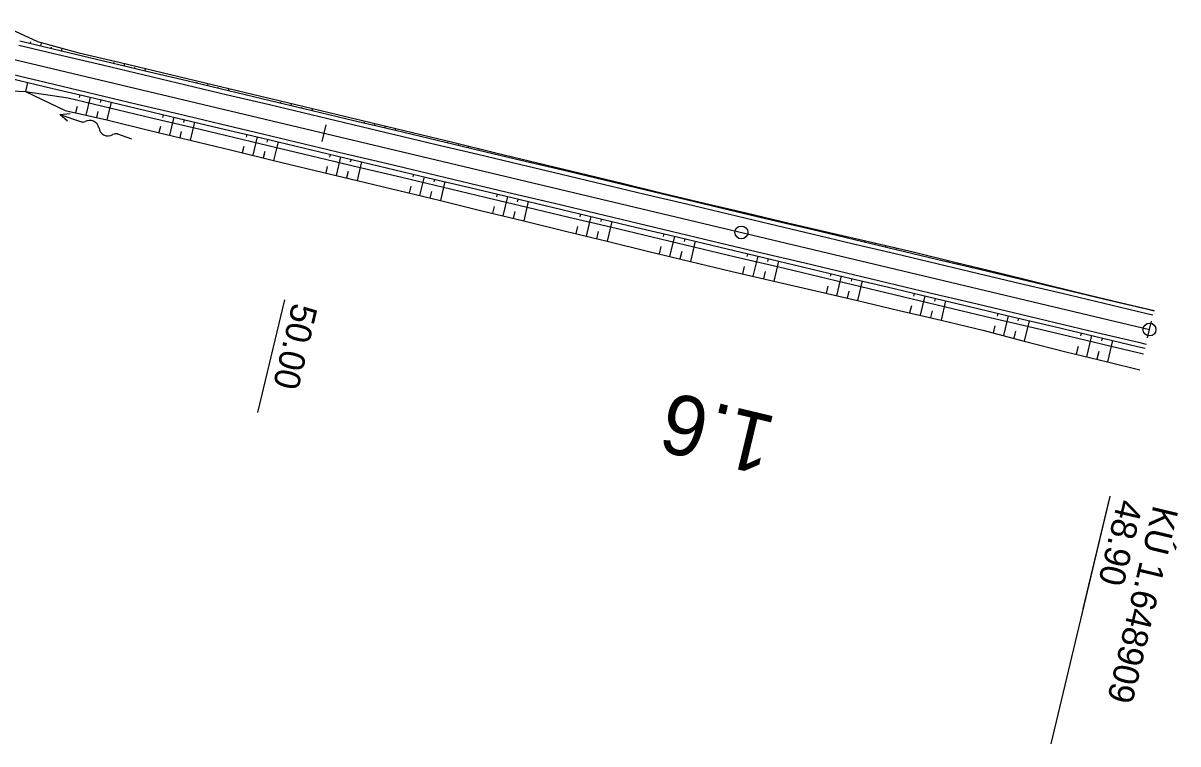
# Model space of a CAD drawing. Extents: x -481656 to -478728, y -1113199 to -1110710.
# Drawn here: x -478863.1 to -478728.5, y -1110802.4 to -1110718.3 of the extents above; entities that cross this region are included whole.
import ezdxf

# ---------------------------------------------------------------- set-up
doc = ezdxf.new("R2010")
doc.units = 0
for name, color, linetype in [('C5_HATCH_SLOPE_L', 7, 'Continuous'), ('C5_HATCH_SLOPE_R', 7, 'Continuous'), ('C5_HECTOMETRY', 7, 'Continuous'), ('C5_HLBODY', 7, 'Continuous'), ('C5_HRANA_TELESO', 7, 'Continuous'), ('C5_KORUNA', 7, 'Continuous'), ('C5_OSA', 7, 'Continuous'), ('C5_PRIKOP', 7, 'Continuous'), ('C5_STANICENI', 7, 'Continuous'), ('C5_ZPEVKRAJ', 7, 'Continuous'), ('DRENÁŽ', 7, 'Continuous'), ('PLYN', 7, 'Continuous')]:
    doc.layers.add(name, color=color, linetype=linetype)

# ---------------------------------------------------------------- blocks, each defined once
blk = doc.blocks.new('A$C70B')
at = {"layer": 'DRENÁŽ'}
for p, q in [((0.87, 0), (-0.87, 0)), ((6.86, 0.43), (7.97, 0)), ((7.97, 0), (5.28, 0)), ((7.97, 0), (6.86, -0.48))]:
    blk.add_line(p, q, dxfattribs=at)
for centre, radius, start, end in [((0.87, 0.58), 0.582, 269.6924, 322.7901), ((2.17, -0.42), 1.05, 24.4039, 142.0836), ((4.08, 0.59), 1.11, 210.8873, 317.3707), ((5.32, -0.64), 0.636, 85.9766, 131.7248)]:
    blk.add_arc(centre, radius, start, end, dxfattribs=at)

msp = doc.modelspace()

# ---------------------------------------------------------------- linework, layer by layer
at = {"layer": 'C5_HATCH_SLOPE_L'}
for p, q in [((-478862.24, -1110720.66), (-478862.2, -1110720.48)), ((-478862.16, -1110720.3), (-478862.16, -1110720.3)), ((-478861.03, -1110720.95), (-478860.95, -1110720.63)), ((-478859.81, -1110721.24), (-478859.78, -1110721.1)), ((-478859.75, -1110720.96), (-478859.75, -1110720.96)), ((-478858.6, -1110721.53), (-478858.54, -1110721.29)), ((-478852.52, -1110722.98), (-478852.49, -1110722.85)), ((-478852.46, -1110722.73), (-478852.46, -1110722.73)), ((-478851.3, -1110723.27), (-478851.24, -1110723.02)), ((-478850.09, -1110723.56), (-478850.06, -1110723.43)), ((-478850.03, -1110723.31), (-478850.03, -1110723.31)), ((-478848.87, -1110723.85), (-478848.81, -1110723.6)), ((-478842.79, -1110725.29), (-478842.76, -1110725.18)), ((-478842.73, -1110725.06), (-478842.73, -1110725.06)), ((-478841.57, -1110725.58), (-478841.52, -1110725.36)), ((-478840.36, -1110725.87), (-478840.33, -1110725.76)), ((-478840.3, -1110725.65), (-478840.3, -1110725.65)), ((-478839.14, -1110726.16), (-478839.09, -1110725.94)), ((-478833.06, -1110727.61), (-478833.04, -1110727.51)), ((-478833.01, -1110727.4), (-478833.01, -1110727.4)), ((-478831.85, -1110727.9), (-478831.8, -1110727.7)), ((-478830.63, -1110728.19), (-478830.61, -1110728.09)), ((-478830.58, -1110727.99), (-478830.58, -1110727.99)), ((-478829.41, -1110728.48), (-478829.37, -1110728.28)), ((-478823.33, -1110729.93), (-478823.31, -1110729.83)), ((-478823.29, -1110729.73), (-478823.29, -1110729.73)), ((-478822.12, -1110730.22), (-478822.07, -1110730.03)), ((-478820.9, -1110730.51), (-478820.88, -1110730.41)), ((-478820.86, -1110730.32), (-478820.86, -1110730.32)), ((-478819.69, -1110730.8), (-478819.64, -1110730.61)), ((-478813.61, -1110732.25), (-478813.59, -1110732.16)), ((-478813.57, -1110732.08), (-478813.57, -1110732.08)), ((-478812.39, -1110732.54), (-478812.35, -1110732.37)), ((-478811.17, -1110732.82), (-478811.16, -1110732.75)), ((-478811.14, -1110732.67), (-478811.14, -1110732.67)), ((-478809.96, -1110733.11), (-478809.92, -1110732.96)), ((-478803.88, -1110734.56), (-478803.86, -1110734.5)), ((-478803.85, -1110734.43), (-478803.85, -1110734.43)), ((-478802.66, -1110734.85), (-478802.63, -1110734.72)), ((-478801.45, -1110735.14), (-478801.43, -1110735.08)), ((-478801.42, -1110735.02), (-478801.42, -1110735.02)), ((-478800.23, -1110735.43), (-478800.2, -1110735.31)), ((-478794.15, -1110736.88), (-478794.14, -1110736.83)), ((-478794.13, -1110736.78), (-478794.13, -1110736.78)), ((-478792.93, -1110737.17), (-478792.91, -1110737.07)), ((-478791.72, -1110737.46), (-478791.71, -1110737.41)), ((-478791.7, -1110737.36), (-478791.7, -1110737.36)), ((-478790.5, -1110737.75), (-478790.48, -1110737.66)), ((-478784.42, -1110739.2), (-478784.41, -1110739.16)), ((-478784.4, -1110739.12), (-478784.4, -1110739.12)), ((-478783.21, -1110739.49), (-478783.19, -1110739.41)), ((-478781.99, -1110739.78), (-478781.98, -1110739.74)), ((-478781.97, -1110739.7), (-478781.97, -1110739.7)), ((-478780.78, -1110740.07), (-478780.76, -1110739.99)), ((-478774.7, -1110741.52), (-478774.68, -1110741.46)), ((-478774.67, -1110741.41), (-478774.67, -1110741.41)), ((-478773.48, -1110741.8), (-478773.45, -1110741.7)), ((-478772.26, -1110742.09), (-478772.25, -1110742.04)), ((-478772.24, -1110741.98), (-478772.24, -1110741.98)), ((-478771.05, -1110742.38), (-478771.02, -1110742.27)), ((-478764.97, -1110743.83), (-478764.95, -1110743.76)), ((-478764.93, -1110743.7), (-478764.93, -1110743.7)), ((-478763.75, -1110744.12), (-478763.72, -1110743.98)), ((-478762.54, -1110744.41), (-478762.52, -1110744.34)), ((-478762.5, -1110744.27), (-478762.5, -1110744.27)), ((-478761.32, -1110744.7), (-478761.28, -1110744.55)), ((-478755.24, -1110746.15), (-478755.22, -1110746.07)), ((-478755.2, -1110745.99), (-478755.2, -1110745.99)), ((-478754.02, -1110746.44), (-478753.99, -1110746.29)), ((-478752.81, -1110746.73), (-478752.79, -1110746.66)), ((-478752.77, -1110746.58), (-478752.77, -1110746.58)), ((-478751.59, -1110747.02), (-478751.56, -1110746.88)), ((-478745.51, -1110748.47), (-478745.5, -1110748.43)), ((-478745.49, -1110748.39), (-478745.49, -1110748.39)), ((-478744.29, -1110748.76), (-478744.28, -1110748.7)), ((-478743.08, -1110749.05), (-478743.08, -1110749.03)), ((-478743.07, -1110749.01), (-478743.07, -1110749.01)), ((-478741.86, -1110749.33), (-478741.86, -1110749.32)), ((-478735.78, -1110750.76), (-478735.78, -1110750.76)), ((-478735.78, -1110750.78), (-478735.78, -1110750.77)), ((-478734.57, -1110751.07), (-478734.56, -1110751.05)), ((-478733.35, -1110751.34), (-478733.35, -1110751.34)), ((-478733.35, -1110751.36), (-478733.35, -1110751.35)), ((-478732.14, -1110751.65), (-478732.13, -1110751.63))]:
    msp.add_line(p, q, dxfattribs=at)
at = {"layer": 'C5_HATCH_SLOPE_R'}
for p, q in [((-478862.57, -1110725.21), (-478862.82, -1110726.29)), ((-478856.49, -1110726.66), (-478856.56, -1110726.98)), ((-478855.27, -1110726.95), (-478855.77, -1110729.04)), ((-478854.05, -1110727.24), (-478854.13, -1110727.56)), ((-478856.81, -1110728.03), (-478856.99, -1110728.76)), ((-478854.38, -1110728.6), (-478854.55, -1110729.32)), ((-478852.84, -1110727.53), (-478853.33, -1110729.6)), ((-478846.76, -1110728.98), (-478846.84, -1110729.3)), ((-478845.54, -1110729.26), (-478846.04, -1110731.36)), ((-478844.33, -1110729.55), (-478844.4, -1110729.88)), ((-478843.11, -1110729.84), (-478843.61, -1110731.95)), ((-478847.09, -1110730.35), (-478847.26, -1110731.07)), ((-478844.65, -1110730.93), (-478844.83, -1110731.66)), ((-478837.03, -1110731.29), (-478837.11, -1110731.62)), ((-478835.82, -1110731.58), (-478836.32, -1110733.72)), ((-478834.6, -1110731.87), (-478834.68, -1110732.2)), ((-478833.38, -1110732.16), (-478833.89, -1110734.31)), ((-478837.36, -1110732.68), (-478837.54, -1110733.43)), ((-478834.93, -1110733.27), (-478835.11, -1110734.01)), ((-478827.3, -1110733.61), (-478827.38, -1110733.93)), ((-478826.09, -1110733.9), (-478826.6, -1110736.07)), ((-478827.64, -1110735.02), (-478827.82, -1110735.78)), ((-478824.87, -1110734.19), (-478824.95, -1110734.51)), ((-478823.66, -1110734.48), (-478824.17, -1110736.65)), ((-478825.21, -1110735.6), (-478825.39, -1110736.36)), ((-478817.58, -1110735.93), (-478817.65, -1110736.25)), ((-478816.36, -1110736.22), (-478816.88, -1110738.41)), ((-478815.14, -1110736.51), (-478815.22, -1110736.83)), ((-478817.91, -1110737.34), (-478818.1, -1110738.11)), ((-478815.48, -1110737.93), (-478815.67, -1110738.71)), ((-478813.93, -1110736.79), (-478814.45, -1110739)), ((-478807.85, -1110738.24), (-478807.92, -1110738.57)), ((-478806.63, -1110738.53), (-478807.17, -1110740.78)), ((-478805.42, -1110738.82), (-478805.49, -1110739.15)), ((-478804.2, -1110739.11), (-478804.74, -1110741.37)), ((-478808.19, -1110739.69), (-478808.38, -1110740.48)), ((-478805.76, -1110740.27), (-478805.95, -1110741.08)), ((-478798.12, -1110740.56), (-478798.2, -1110740.89)), ((-478798.47, -1110742.03), (-478798.67, -1110742.85)), ((-478796.9, -1110740.85), (-478797.45, -1110743.15)), ((-478795.69, -1110741.14), (-478795.76, -1110741.46)), ((-478794.47, -1110741.43), (-478795.02, -1110743.74)), ((-478796.04, -1110742.62), (-478796.24, -1110743.45)), ((-478788.39, -1110742.88), (-478788.47, -1110743.2)), ((-478787.17, -1110743.17), (-478787.73, -1110745.52)), ((-478788.75, -1110744.37), (-478788.95, -1110745.22)), ((-478785.96, -1110743.46), (-478786.04, -1110743.78)), ((-478784.74, -1110743.75), (-478785.31, -1110746.11)), ((-478786.32, -1110744.96), (-478786.52, -1110745.81)), ((-478778.66, -1110745.2), (-478778.74, -1110745.52)), ((-478777.45, -1110745.49), (-478778.01, -1110747.83)), ((-478776.23, -1110745.77), (-478776.31, -1110746.1)), ((-478775.02, -1110746.06), (-478775.57, -1110748.4)), ((-478779.02, -1110746.7), (-478779.22, -1110747.55)), ((-478776.59, -1110747.27), (-478776.79, -1110748.12)), ((-478768.94, -1110747.51), (-478769.01, -1110747.84)), ((-478767.72, -1110747.8), (-478768.27, -1110750.11)), ((-478766.5, -1110748.09), (-478766.58, -1110748.42)), ((-478765.29, -1110748.38), (-478765.83, -1110750.67)), ((-478769.29, -1110748.99), (-478769.49, -1110749.82)), ((-478766.85, -1110749.56), (-478767.05, -1110750.39)), ((-478759.21, -1110749.83), (-478759.29, -1110750.15)), ((-478757.99, -1110750.12), (-478758.53, -1110752.37)), ((-478759.55, -1110751.28), (-478759.75, -1110752.09)), ((-478756.78, -1110750.41), (-478756.85, -1110750.73)), ((-478755.56, -1110750.7), (-478756.09, -1110752.94)), ((-478757.12, -1110751.86), (-478757.31, -1110752.65)), ((-478749.48, -1110752.15), (-478749.56, -1110752.47)), ((-478748.26, -1110752.44), (-478748.82, -1110754.75)), ((-478747.05, -1110752.73), (-478747.12, -1110753.05)), ((-478749.83, -1110753.61), (-478750.02, -1110754.43)), ((-478745.83, -1110753.02), (-478746.4, -1110755.4)), ((-478747.41, -1110754.22), (-478747.61, -1110755.07)), ((-478739.75, -1110754.46), (-478739.83, -1110754.79)), ((-478738.54, -1110754.75), (-478739.13, -1110757.23)), ((-478737.32, -1110755.04), (-478737.4, -1110755.37)), ((-478736.1, -1110755.33), (-478736.7, -1110757.81)), ((-478740.12, -1110756.02), (-478740.34, -1110756.94)), ((-478737.69, -1110756.61), (-478737.91, -1110757.52))]:
    msp.add_line(p, q, dxfattribs=at)
at = {"layer": 'C5_HECTOMETRY'}
msp.add_circle((-478779.36, -1110742.72), 0.75, dxfattribs=at)
at = {"layer": 'C5_HLBODY'}
msp.add_line((-478736.41, -1110773.51), (-478743.3, -1110802.4), dxfattribs=at)
msp.add_circle((-478731.78, -1110754.05), 0.75, dxfattribs=at)
at = {"layer": 'C5_HRANA_TELESO'}
for p, q in [((-478866.06, -1110718.29), (-478861.43, -1110720.45)), ((-478861.43, -1110720.45), (-478856.6, -1110721.75)), ((-478856.6, -1110721.75), (-478851.73, -1110722.88)), ((-478851.73, -1110722.88), (-478846.87, -1110724.05)), ((-478846.87, -1110724.05), (-478842.01, -1110725.22)), ((-478842.01, -1110725.22), (-478837.15, -1110726.4)), ((-478867.9, -1110726), (-478862.82, -1110726.29)), ((-478862.82, -1110726.29), (-478858.21, -1110728.48)), ((-478837.15, -1110726.4), (-478832.29, -1110727.57)), ((-478858.21, -1110728.48), (-478853.33, -1110729.6)), ((-478832.29, -1110727.57), (-478827.43, -1110728.73)), ((-478853.33, -1110729.6), (-478848.47, -1110730.77)), ((-478827.43, -1110728.73), (-478822.56, -1110729.89)), ((-478822.56, -1110729.89), (-478817.7, -1110731.07)), ((-478848.47, -1110730.77), (-478843.61, -1110731.95)), ((-478817.7, -1110731.07), (-478812.84, -1110732.24)), ((-478843.61, -1110731.95), (-478838.75, -1110733.13)), ((-478812.84, -1110732.24), (-478807.98, -1110733.42)), ((-478838.75, -1110733.13), (-478833.89, -1110734.31)), ((-478807.98, -1110733.42), (-478803.12, -1110734.59)), ((-478833.89, -1110734.31), (-478829.04, -1110735.49)), ((-478803.12, -1110734.59), (-478798.26, -1110735.77)), ((-478829.04, -1110735.49), (-478824.17, -1110736.65)), ((-478824.17, -1110736.65), (-478819.31, -1110737.82)), ((-478798.26, -1110735.77), (-478793.4, -1110736.94)), ((-478819.31, -1110737.82), (-478814.45, -1110739)), ((-478793.4, -1110736.94), (-478788.54, -1110738.12)), ((-478814.45, -1110739), (-478809.6, -1110740.19)), ((-478788.54, -1110738.12), (-478783.68, -1110739.29)), ((-478783.68, -1110739.29), (-478778.82, -1110740.44)), ((-478809.6, -1110740.19), (-478804.74, -1110741.37)), ((-478778.82, -1110740.44), (-478773.95, -1110741.58)), ((-478804.74, -1110741.37), (-478799.88, -1110742.56)), ((-478773.95, -1110741.58), (-478769.08, -1110742.72)), ((-478799.88, -1110742.56), (-478795.02, -1110743.74)), ((-478769.08, -1110742.72), (-478764.21, -1110743.86)), ((-478795.02, -1110743.74), (-478790.16, -1110744.93)), ((-478764.21, -1110743.86), (-478759.34, -1110745)), ((-478790.16, -1110744.93), (-478785.31, -1110746.11)), ((-478785.31, -1110746.11), (-478780.44, -1110747.26)), ((-478759.34, -1110745), (-478754.48, -1110746.17)), ((-478780.44, -1110747.26), (-478775.57, -1110748.4)), ((-478754.48, -1110746.17), (-478749.62, -1110747.35)), ((-478749.62, -1110747.35), (-478744.77, -1110748.57)), ((-478775.57, -1110748.4), (-478770.7, -1110749.54)), ((-478744.77, -1110748.57), (-478739.92, -1110749.76)), ((-478770.7, -1110749.54), (-478765.83, -1110750.67)), ((-478739.92, -1110749.76), (-478735.06, -1110750.95)), ((-478765.83, -1110750.67), (-478760.96, -1110751.81)), ((-478735.06, -1110750.95), (-478731.26, -1110751.83)), ((-478760.96, -1110751.81), (-478756.09, -1110752.94)), ((-478756.09, -1110752.94), (-478751.23, -1110754.11)), ((-478751.23, -1110754.11), (-478746.4, -1110755.4)), ((-478746.4, -1110755.4), (-478741.56, -1110756.65)), ((-478741.56, -1110756.65), (-478736.7, -1110757.81)), ((-478736.7, -1110757.81), (-478732.91, -1110758.76))]:
    msp.add_line(p, q, dxfattribs=at)
at = {"layer": 'C5_KORUNA'}
for p, q in [((-478863.46, -1110720.37), (-478858.6, -1110721.53)), ((-478858.6, -1110721.53), (-478853.73, -1110722.69)), ((-478853.73, -1110722.69), (-478848.87, -1110723.85)), ((-478848.87, -1110723.85), (-478844.01, -1110725.01)), ((-478864.5, -1110724.75), (-478859.64, -1110725.91)), ((-478859.64, -1110725.91), (-478854.78, -1110727.06)), ((-478844.01, -1110725.01), (-478839.14, -1110726.16)), ((-478854.78, -1110727.06), (-478849.91, -1110728.22)), ((-478839.14, -1110726.16), (-478834.28, -1110727.32)), ((-478849.91, -1110728.22), (-478845.05, -1110729.38)), ((-478834.28, -1110727.32), (-478829.41, -1110728.48)), ((-478829.41, -1110728.48), (-478824.55, -1110729.64)), ((-478845.05, -1110729.38), (-478840.18, -1110730.54)), ((-478824.55, -1110729.64), (-478819.69, -1110730.8)), ((-478840.18, -1110730.54), (-478835.32, -1110731.7)), ((-478819.69, -1110730.8), (-478814.82, -1110731.96)), ((-478835.32, -1110731.7), (-478830.46, -1110732.86)), ((-478814.82, -1110731.96), (-478809.96, -1110733.11)), ((-478830.46, -1110732.86), (-478825.59, -1110734.02)), ((-478809.96, -1110733.11), (-478805.09, -1110734.27)), ((-478825.59, -1110734.02), (-478820.73, -1110735.18)), ((-478820.73, -1110735.18), (-478815.86, -1110736.33)), ((-478805.09, -1110734.27), (-478800.23, -1110735.43)), ((-478815.86, -1110736.33), (-478811, -1110737.49)), ((-478800.23, -1110735.43), (-478795.37, -1110736.59)), ((-478795.37, -1110736.59), (-478790.5, -1110737.75)), ((-478811, -1110737.49), (-478806.14, -1110738.65)), ((-478790.5, -1110737.75), (-478785.64, -1110738.91)), ((-478806.14, -1110738.65), (-478801.27, -1110739.81)), ((-478785.64, -1110738.91), (-478780.78, -1110740.07)), ((-478801.27, -1110739.81), (-478796.41, -1110740.97)), ((-478780.78, -1110740.07), (-478775.91, -1110741.23)), ((-478796.41, -1110740.97), (-478791.54, -1110742.13)), ((-478775.91, -1110741.23), (-478771.05, -1110742.38)), ((-478791.54, -1110742.13), (-478786.68, -1110743.28)), ((-478786.68, -1110743.28), (-478781.82, -1110744.44)), ((-478771.05, -1110742.38), (-478766.18, -1110743.54)), ((-478781.82, -1110744.44), (-478776.95, -1110745.6)), ((-478766.18, -1110743.54), (-478761.32, -1110744.7)), ((-478761.32, -1110744.7), (-478756.46, -1110745.86)), ((-478776.95, -1110745.6), (-478772.09, -1110746.76)), ((-478756.46, -1110745.86), (-478751.59, -1110747.02)), ((-478772.09, -1110746.76), (-478767.23, -1110747.92)), ((-478751.59, -1110747.02), (-478746.73, -1110748.18)), ((-478767.23, -1110747.92), (-478762.36, -1110749.08)), ((-478746.73, -1110748.18), (-478741.86, -1110749.33)), ((-478762.36, -1110749.08), (-478757.5, -1110750.24)), ((-478741.86, -1110749.33), (-478737, -1110750.49)), ((-478757.5, -1110750.24), (-478752.63, -1110751.4)), ((-478752.63, -1110751.4), (-478747.77, -1110752.55)), ((-478737, -1110750.49), (-478732.14, -1110751.65)), ((-478747.77, -1110752.55), (-478742.91, -1110753.71)), ((-478732.14, -1110751.65), (-478731.26, -1110751.86)), ((-478742.91, -1110753.71), (-478738.04, -1110754.87)), ((-478738.04, -1110754.87), (-478733.18, -1110756.03)), ((-478733.18, -1110756.03), (-478732.3, -1110756.24))]:
    msp.add_line(p, q, dxfattribs=at)
at = {"layer": 'C5_OSA'}
msp.add_line((-478877.17, -1110719.42), (-478731.78, -1110754.05), dxfattribs=at)
at = {"layer": 'C5_PRIKOP'}
for p, q in [((-478862.82, -1110726.29), (-478857.86, -1110727.02)), ((-478857.86, -1110727.02), (-478852.99, -1110728.18)), ((-478852.99, -1110728.18), (-478848.13, -1110729.33)), ((-478848.13, -1110729.33), (-478843.27, -1110730.49)), ((-478843.27, -1110730.49), (-478838.4, -1110731.65)), ((-478838.4, -1110731.65), (-478833.54, -1110732.81)), ((-478833.54, -1110732.81), (-478828.67, -1110733.97)), ((-478828.67, -1110733.97), (-478823.81, -1110735.13)), ((-478823.81, -1110735.13), (-478818.95, -1110736.28)), ((-478818.95, -1110736.28), (-478814.08, -1110737.44)), ((-478814.08, -1110737.44), (-478809.22, -1110738.6)), ((-478809.22, -1110738.6), (-478804.35, -1110739.76)), ((-478804.35, -1110739.76), (-478799.49, -1110740.92)), ((-478799.49, -1110740.92), (-478794.63, -1110742.08)), ((-478794.63, -1110742.08), (-478789.76, -1110743.24)), ((-478789.76, -1110743.24), (-478784.9, -1110744.4)), ((-478784.9, -1110744.4), (-478780.03, -1110745.55)), ((-478780.03, -1110745.55), (-478775.17, -1110746.71)), ((-478775.17, -1110746.71), (-478770.31, -1110747.87)), ((-478770.31, -1110747.87), (-478765.44, -1110749.03)), ((-478765.44, -1110749.03), (-478760.58, -1110750.19)), ((-478760.58, -1110750.19), (-478755.71, -1110751.35)), ((-478755.71, -1110751.35), (-478750.85, -1110752.51)), ((-478750.85, -1110752.51), (-478745.99, -1110753.66)), ((-478745.99, -1110753.66), (-478741.12, -1110754.82)), ((-478741.12, -1110754.82), (-478736.26, -1110755.98)), ((-478736.26, -1110755.98), (-478732.47, -1110756.89))]:
    msp.add_line(p, q, dxfattribs=at)
at = {"layer": 'C5_STANICENI'}
for p, q in [((-478828.23, -1110732.1), (-478827.77, -1110730.16)), ((-478832.63, -1110750.59), (-478835.76, -1110763.72)), ((-478732.02, -1110755.02), (-478731.56, -1110753.07)), ((-478736.42, -1110773.5), (-478739.55, -1110786.64))]:
    msp.add_line(p, q, dxfattribs=at)
at = {"layer": 'C5_ZPEVKRAJ'}
for p, q in [((-478863.58, -1110720.86), (-478858.71, -1110722.02)), ((-478858.71, -1110722.02), (-478853.85, -1110723.17)), ((-478853.85, -1110723.17), (-478848.98, -1110724.33)), ((-478864.39, -1110724.26), (-478859.52, -1110725.42)), ((-478848.98, -1110724.33), (-478844.12, -1110725.49)), ((-478859.52, -1110725.42), (-478854.66, -1110726.58)), ((-478844.12, -1110725.49), (-478839.26, -1110726.65)), ((-478854.66, -1110726.58), (-478849.8, -1110727.74)), ((-478839.26, -1110726.65), (-478834.39, -1110727.81)), ((-478849.8, -1110727.74), (-478844.93, -1110728.9)), ((-478834.39, -1110727.81), (-478829.53, -1110728.97)), ((-478844.93, -1110728.9), (-478840.07, -1110730.05)), ((-478829.53, -1110728.97), (-478824.67, -1110730.12)), ((-478840.07, -1110730.05), (-478835.2, -1110731.21)), ((-478835.2, -1110731.21), (-478830.34, -1110732.37)), ((-478824.67, -1110730.12), (-478819.8, -1110731.28)), ((-478819.8, -1110731.28), (-478814.94, -1110732.44)), ((-478830.34, -1110732.37), (-478825.48, -1110733.53)), ((-478814.94, -1110732.44), (-478810.07, -1110733.6)), ((-478825.48, -1110733.53), (-478820.61, -1110734.69)), ((-478810.07, -1110733.6), (-478805.21, -1110734.76)), ((-478820.61, -1110734.69), (-478815.75, -1110735.85)), ((-478805.21, -1110734.76), (-478800.35, -1110735.92)), ((-478815.75, -1110735.85), (-478810.89, -1110737.01)), ((-478800.35, -1110735.92), (-478795.48, -1110737.08)), ((-478810.89, -1110737.01), (-478806.02, -1110738.17)), ((-478795.48, -1110737.08), (-478790.62, -1110738.24)), ((-478806.02, -1110738.17), (-478801.16, -1110739.32)), ((-478801.16, -1110739.32), (-478796.29, -1110740.48)), ((-478790.62, -1110738.24), (-478785.75, -1110739.39)), ((-478796.29, -1110740.48), (-478791.43, -1110741.64)), ((-478785.75, -1110739.39), (-478780.89, -1110740.55)), ((-478780.89, -1110740.55), (-478776.03, -1110741.71)), ((-478791.43, -1110741.64), (-478786.57, -1110742.8)), ((-478776.03, -1110741.71), (-478771.16, -1110742.87)), ((-478786.57, -1110742.8), (-478781.7, -1110743.96)), ((-478771.16, -1110742.87), (-478766.3, -1110744.03)), ((-478781.7, -1110743.96), (-478776.84, -1110745.12)), ((-478766.3, -1110744.03), (-478761.43, -1110745.19)), ((-478776.84, -1110745.12), (-478771.97, -1110746.27)), ((-478761.43, -1110745.19), (-478756.57, -1110746.35)), ((-478771.97, -1110746.27), (-478767.11, -1110747.43)), ((-478767.11, -1110747.43), (-478762.25, -1110748.59)), ((-478756.57, -1110746.35), (-478751.71, -1110747.5)), ((-478762.25, -1110748.59), (-478757.38, -1110749.75)), ((-478751.71, -1110747.5), (-478746.84, -1110748.66)), ((-478746.84, -1110748.66), (-478741.98, -1110749.82)), ((-478757.38, -1110749.75), (-478752.52, -1110750.91)), ((-478741.98, -1110749.82), (-478737.11, -1110750.98)), ((-478752.52, -1110750.91), (-478747.65, -1110752.07)), ((-478737.11, -1110750.98), (-478732.25, -1110752.14)), ((-478747.65, -1110752.07), (-478742.79, -1110753.23)), ((-478732.25, -1110752.14), (-478731.38, -1110752.35)), ((-478742.79, -1110753.23), (-478737.93, -1110754.39)), ((-478737.93, -1110754.39), (-478733.06, -1110755.54)), ((-478733.06, -1110755.54), (-478732.19, -1110755.75))]:
    msp.add_line(p, q, dxfattribs=at)

# ---------------------------------------------------------------- block references
at = {"layer": 'PLYN', "rotation": 161.33490466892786}
msp.add_blockref('A$C70B', (-478851.28, -1110731.51), dxfattribs=at)

# ---------------------------------------------------------------- texts
at = {"layer": 'C5_HECTOMETRY'}
msp.add_text('1.6', height=6.999, rotation=166.5561, dxfattribs=at).set_placement((-478775.04, -1110764.31))
at = {"layer": 'C5_HLBODY'}
msp.add_text('KÚ 1.648909', height=2.999, rotation=256.6017, dxfattribs=at).set_placement((-478731.32, -1110774.44))
at = {"layer": 'C5_STANICENI'}
for s, p in [('50.00', (-478831.66, -1110750.82)), ('48.90', (-478735.45, -1110773.73))]:
    msp.add_text(s, height=2.999, rotation=256.6017, dxfattribs=at).set_placement(p)

doc.saveas('drawing.dxf')
